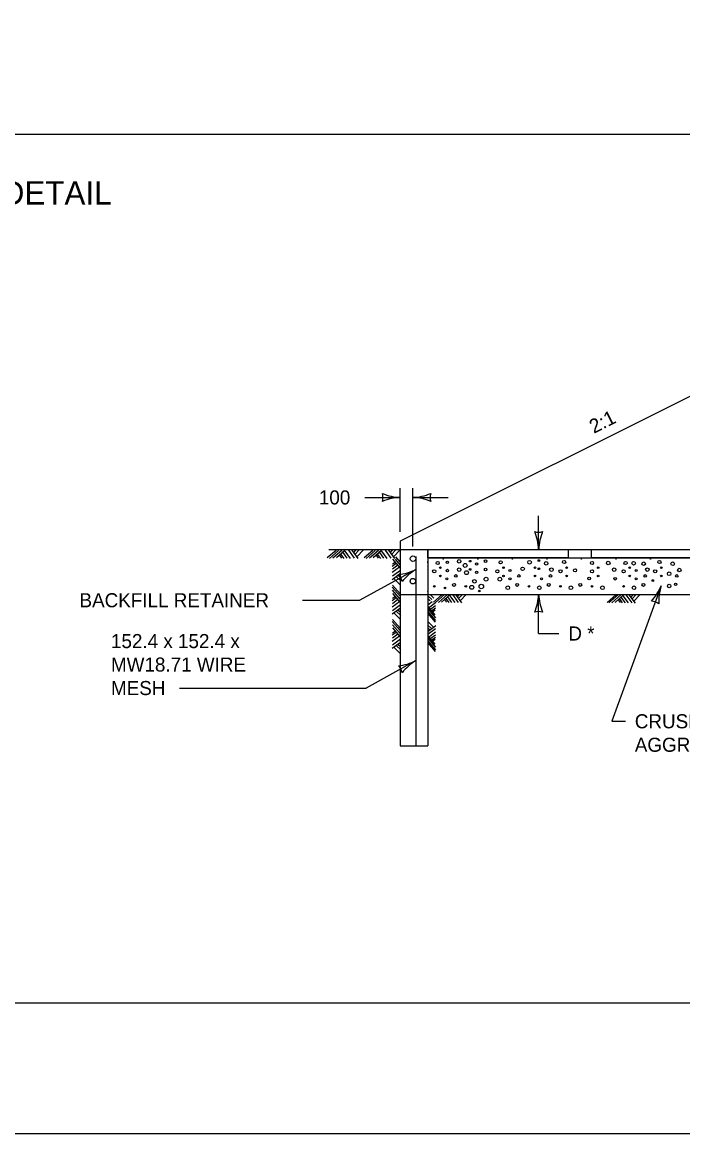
# Model space of a CAD drawing. Extents: x 49991.4 to 50021, y 49987.6 to 50011.4.
# Drawn here: x 50006.879 to 50009.692, y 49987.799 to 49992.532 of the extents above; entities that cross this region are included whole.
import ezdxf

# ---------------------------------------------------------------- set-up
doc = ezdxf.new("R2010")
doc.units = 0
for name, color, linetype in [('Level 1', 7, 'Continuous'), ('Level 2', 7, 'Continuous'), ('Level 3', 7, 'Continuous')]:
    doc.layers.add(name, color=color, linetype=linetype)

msp = doc.modelspace()

# ---------------------------------------------------------------- linework, layer by layer
at = {"layer": 'Level 1'}
for p, q in [((50010.2683, 49991.2116), (50008.4885, 49990.3217)), ((50008.2151, 49990.2827), (50008.1781, 49990.2505)), ((50008.1844, 49990.287), (50008.6055, 49990.287)), ((50008.226, 49990.2827), (50008.1871, 49990.2488)), ((50008.2398, 49990.2829), (50008.2018, 49990.2498)), ((50008.253, 49990.2831), (50008.2167, 49990.2515)), ((50008.2678, 49990.2835), (50008.2923, 49990.2498)), ((50008.2821, 49990.2837), (50008.3081, 49990.248)), ((50008.2891, 49990.2722), (50008.2999, 49990.2837)), ((50008.2956, 49990.2654), (50008.3139, 49990.2847)), ((50008.3051, 49990.2563), (50008.3305, 49990.2833)), ((50008.3715, 49990.2827), (50008.3344, 49990.2505)), ((50008.3824, 49990.2827), (50008.3435, 49990.2488)), ((50008.3962, 49990.2829), (50008.3581, 49990.2498)), ((50008.4094, 49990.2831), (50008.3729, 49990.2515)), ((50008.424, 49990.2835), (50008.4486, 49990.2498)), ((50008.4383, 49990.2837), (50008.4645, 49990.248)), ((50008.4454, 49990.2722), (50008.4562, 49990.2837)), ((50008.4519, 49990.2654), (50008.4701, 49990.2847)), ((50008.4615, 49990.2563), (50008.4869, 49990.2833)), ((50008.4885, 49990.3217), (50008.4885, 49989.4513)), ((50008.4885, 49990.2827), (50008.4885, 49990.2827)), ((50008.6055, 49990.287), (50008.6055, 49989.4513)), ((50008.6055, 49990.287), (50010.568, 49990.287)), ((50008.6055, 49990.287), (50009.2036, 49990.287)), ((50008.6055, 49990.2515), (50008.6055, 49990.287)), ((50009.2036, 49990.287), (50009.2036, 49990.2515)), ((50009.303, 49990.2515), (50009.303, 49990.287)), ((50009.303, 49990.287), (50010.568, 49990.287)), ((50008.2295, 49990.2621), (50008.238, 49990.2504)), ((50008.2357, 49990.266), (50008.2482, 49990.2488)), ((50008.2435, 49990.2732), (50008.2608, 49990.2494)), ((50008.2531, 49990.2797), (50008.2757, 49990.2488)), ((50008.3859, 49990.2621), (50008.3944, 49990.2504)), ((50008.3921, 49990.266), (50008.4046, 49990.2488)), ((50008.3998, 49990.2732), (50008.4172, 49990.2494)), ((50008.4094, 49990.2797), (50008.4319, 49990.2488)), ((50008.4889, 49990.2092), (50008.4573, 49990.2456)), ((50008.4887, 49990.2216), (50008.4682, 49990.2451)), ((50008.4885, 49990.2344), (50008.4703, 49990.2553)), ((50008.5553, 49990.257), (50008.5553, 49989.4513)), ((50008.6055, 49990.2515), (50010.568, 49990.2515)), ((50009.2036, 49990.2515), (50008.6055, 49990.2515)), ((50008.6055, 49990.2472), (50008.6055, 49990.2472)), ((50010.568, 49990.2515), (50009.303, 49990.2515)), ((50008.4717, 49990.227), (50008.4546, 49990.2144)), ((50008.4855, 49990.211), (50008.4546, 49990.1885)), ((50008.4789, 49990.2198), (50008.4551, 49990.2025)), ((50008.4892, 49990.1973), (50008.4556, 49990.1727)), ((50008.4678, 49990.2326), (50008.4562, 49990.2241)), ((50008.4895, 49990.1839), (50008.4538, 49990.1579)), ((50008.4621, 49990.1623), (50008.4889, 49990.1369)), ((50008.4712, 49990.1711), (50008.4905, 49990.1527)), ((50008.478, 49990.1768), (50008.4894, 49990.166)), ((50008.4885, 49990.0879), (50008.4546, 49990.1268)), ((50008.4887, 49990.0749), (50008.4556, 49990.113)), ((50008.4885, 49990.0982), (50008.4562, 49990.1352)), ((50008.4889, 49990.0627), (50008.4573, 49990.0991)), ((50008.4885, 49990.0955), (50010.568, 49990.0955)), ((50008.6319, 49990.0801), (50008.6156, 49990.0955)), ((50008.6675, 49990.0944), (50008.6305, 49990.0621)), ((50008.6773, 49990.0944), (50008.6384, 49990.0604)), ((50008.6896, 49990.0945), (50008.6515, 49990.0614)), ((50008.7012, 49990.0948), (50008.6648, 49990.063)), ((50008.711, 49990.0951), (50008.7355, 49990.0615)), ((50008.7236, 49990.0953), (50008.7497, 49990.0597)), ((50008.7307, 49990.0839), (50008.7415, 49990.0953)), ((50008.7361, 49990.077), (50008.7536, 49990.0955)), ((50008.7442, 49990.0678), (50008.7697, 49990.0948)), ((50009.4285, 49990.0931), (50009.3904, 49990.06)), ((50009.4401, 49990.0934), (50009.4037, 49990.0616)), ((50009.4499, 49990.0937), (50009.4745, 49990.0601)), ((50009.4627, 49990.0939), (50009.4887, 49990.0583)), ((50009.4697, 49990.0825), (50009.4805, 49990.0939)), ((50009.475, 49990.0756), (50009.4934, 49990.095)), ((50009.4832, 49990.0664), (50009.5086, 49990.0934)), ((50008.4717, 49990.0805), (50008.4546, 49990.0679)), ((50008.4855, 49990.0644), (50008.4546, 49990.0418)), ((50008.4789, 49990.0733), (50008.4551, 49990.056)), ((50008.4892, 49990.0507), (50008.4556, 49990.0262)), ((50008.4678, 49990.0861), (50008.4562, 49990.0776)), ((50008.6227, 49990.0731), (50008.6055, 49990.0894)), ((50008.6159, 49990.0687), (50008.6055, 49990.0786)), ((50008.6055, 49990.0508), (50008.6244, 49990.0646)), ((50008.6085, 49990.0388), (50008.6393, 49990.0613)), ((50008.6151, 49990.0316), (50008.6388, 49990.0489)), ((50008.6778, 49990.0737), (50008.6863, 49990.0621)), ((50008.6832, 49990.0776), (50008.6957, 49990.0604)), ((50008.6898, 49990.0848), (50008.7071, 49990.061)), ((50008.6981, 49990.0914), (50008.7206, 49990.0605)), ((50009.4064, 49990.093), (50009.3694, 49990.0607)), ((50009.4162, 49990.093), (50009.3773, 49990.059)), ((50009.4168, 49990.0723), (50009.4252, 49990.0607)), ((50009.4221, 49990.0762), (50009.4346, 49990.059)), ((50009.4287, 49990.0834), (50009.4461, 49990.0596)), ((50009.437, 49990.09), (50009.4595, 49990.0591)), ((50008.4895, 49990.0374), (50008.4538, 49990.0113)), ((50008.4621, 49990.0158), (50008.4889, 49989.9903)), ((50008.4712, 49990.0244), (50008.4905, 49990.0062)), ((50008.478, 49990.0303), (50008.4894, 49990.0195)), ((50008.6055, 49990.044), (50008.6367, 49990.0082)), ((50008.6055, 49990.034), (50008.6383, 49989.9962)), ((50008.6055, 49990.0232), (50008.6393, 49989.9845)), ((50008.6055, 49990.0143), (50008.6377, 49989.9774)), ((50008.6223, 49990.0259), (50008.6393, 49990.0383)), ((50008.6261, 49990.0213), (50008.6377, 49990.0298)), ((50008.4885, 49989.9414), (50008.4546, 49989.9803)), ((50008.4887, 49989.9284), (50008.4556, 49989.9665)), ((50008.4885, 49989.9517), (50008.4562, 49989.9887)), ((50008.4889, 49989.9162), (50008.4573, 49989.9525)), ((50008.6319, 49989.9551), (50008.6055, 49989.98)), ((50008.6227, 49989.9482), (50008.6055, 49989.9645)), ((50008.6055, 49989.9374), (50008.6401, 49989.9626)), ((50008.6159, 49989.9438), (50008.6055, 49989.9537)), ((50008.4717, 49989.9338), (50008.4546, 49989.9213)), ((50008.4855, 49989.9179), (50008.4546, 49989.8953)), ((50008.4789, 49989.9267), (50008.4551, 49989.9093)), ((50008.4892, 49989.9042), (50008.4556, 49989.8797)), ((50008.4678, 49989.9396), (50008.4562, 49989.9311)), ((50008.6055, 49989.9259), (50008.6383, 49989.9499)), ((50008.6055, 49989.9191), (50008.6367, 49989.8832)), ((50008.6055, 49989.9089), (50008.6383, 49989.8712)), ((50008.6085, 49989.9138), (50008.6393, 49989.9363)), ((50008.6151, 49989.9066), (50008.6388, 49989.924)), ((50008.6223, 49989.9009), (50008.6393, 49989.9134)), ((50008.6261, 49989.8964), (50008.6377, 49989.9049)), ((50008.4895, 49989.8909), (50008.4538, 49989.8648)), ((50008.4621, 49989.8693), (50008.4889, 49989.8437)), ((50008.4712, 49989.8779), (50008.4905, 49989.8597)), ((50008.478, 49989.8838), (50008.4894, 49989.873)), ((50008.6055, 49989.8983), (50008.6393, 49989.8594)), ((50008.6055, 49989.8894), (50008.6377, 49989.8523)), ((50008.4885, 49989.6899), (50008.4885, 49989.6899)), ((50008.4885, 49989.4513), (50008.6055, 49989.4513))]:
    msp.add_line(p, q, dxfattribs=at)
for points in [[(49999.3835, 49998.9992), (50016.7501, 49998.9992), (50016.7501, 49987.7988), (49999.3835, 49987.7988)], [(49999.5613, 49992.0549), (50014.5211, 49992.0549), (50014.5211, 49988.3552), (49999.5613, 49988.3552)]]:
    msp.add_lwpolyline(points, close=True, dxfattribs=at)
for centre, radius in [((50008.5429, 49990.2475), 0.0116), ((50008.6482, 49990.229), 0.00684), ((50008.6893, 49990.232), 0.00552), ((50008.7395, 49990.2361), 0.00765), ((50008.7863, 49990.2369), 0.00341), ((50008.8522, 49990.2369), 0.00552), ((50008.9164, 49990.2319), 0.00684), ((50009.0396, 49990.2323), 0.00765), ((50009.0793, 49990.2397), 0.00346), ((50009.1102, 49990.2276), 0.00765), ((50009.1867, 49990.2333), 0.00684), ((50009.3056, 49990.229), 0.00684), ((50009.3746, 49990.229), 0.00765), ((50009.4485, 49990.229), 0.00684), ((50009.4829, 49990.2282), 0.00766), ((50009.5928, 49990.2333), 0.00684), ((50008.6335, 49990.1939), 0.00684), ((50008.6595, 49990.2092), 0.00341), ((50008.6893, 49990.1968), 0.00552), ((50008.7395, 49990.2009), 0.00765), ((50008.7654, 49990.2189), 0.00824), ((50008.771, 49990.1879), 0.00824), ((50008.7863, 49990.2017), 0.00341), ((50008.8139, 49990.2246), 0.0046), ((50008.8139, 49990.1895), 0.0046), ((50008.8522, 49990.2017), 0.00552), ((50008.9023, 49990.1939), 0.00684), ((50008.9284, 49990.2092), 0.00341), ((50008.9559, 49990.197), 0.0046), ((50009.0101, 49990.2042), 0.00765), ((50009.0628, 49990.2092), 0.00341), ((50009.0793, 49990.2045), 0.00346), ((50009.1327, 49990.2009), 0.00765), ((50009.1712, 49990.1939), 0.00684), ((50009.1972, 49990.2092), 0.00341), ((50009.2331, 49990.1981), 0.00684), ((50009.3056, 49990.1939), 0.00684), ((50009.3317, 49990.2092), 0.00341), ((50009.3999, 49990.2009), 0.00765), ((50009.4401, 49990.1939), 0.00684), ((50009.4661, 49990.2092), 0.00341), ((50009.4937, 49990.197), 0.0046), ((50009.5257, 49990.2261), 0.00765), ((50009.5411, 49990.2008), 0.00765), ((50009.5745, 49990.1939), 0.00684), ((50009.6005, 49990.2092), 0.00341), ((50009.6342, 49990.1832), 0.00766), ((50009.6491, 49990.2259), 0.00765), ((50009.6773, 49990.1992), 0.00765), ((50008.5424, 49990.1518), 0.0116), ((50008.6595, 49990.174), 0.00341), ((50008.6871, 49990.1618), 0.0046), ((50008.7177, 49990.1359), 0.00613), ((50008.7253, 49990.174), 0.00552), ((50008.8047, 49990.1513), 0.00766), ((50008.8543, 49990.1603), 0.00824), ((50008.913, 49990.1603), 0.00824), ((50008.9284, 49990.174), 0.00341), ((50008.9559, 49990.1618), 0.0046), ((50008.9866, 49990.1359), 0.00613), ((50008.9942, 49990.174), 0.00552), ((50009.0628, 49990.174), 0.00341), ((50009.0904, 49990.1618), 0.0046), ((50009.121, 49990.1359), 0.00613), ((50009.1286, 49990.174), 0.00552), ((50009.1972, 49990.174), 0.00341), ((50009.2554, 49990.1359), 0.00613), ((50009.2932, 49990.1634), 0.00552), ((50009.3317, 49990.174), 0.00341), ((50009.4043, 49990.1622), 0.00552), ((50009.4661, 49990.174), 0.00341), ((50009.4937, 49990.1618), 0.0046), ((50009.5243, 49990.1359), 0.00613), ((50009.532, 49990.174), 0.00552), ((50009.5646, 49990.1544), 0.00341), ((50009.6005, 49990.174), 0.00341), ((50009.6618, 49990.1382), 0.00552), ((50009.6664, 49990.174), 0.00552), ((50008.6335, 49990.1298), 0.00341), ((50008.6794, 49990.123), 0.00341), ((50008.7679, 49990.1298), 0.00341), ((50008.7932, 49990.1256), 0.00824), ((50008.8254, 49990.1096), 0.00341), ((50008.834, 49990.1288), 0.00968), ((50008.9467, 49990.1237), 0.00766), ((50009.0368, 49990.1298), 0.00341), ((50009.0812, 49990.1237), 0.00766), ((50009.1712, 49990.1298), 0.00341), ((50009.2156, 49990.1237), 0.00766), ((50009.3056, 49990.1298), 0.00341), ((50009.35, 49990.1237), 0.00766), ((50009.4401, 49990.1298), 0.00341), ((50009.4845, 49990.1237), 0.00766), ((50009.6342, 49990.1312), 0.00766)]:
    msp.add_circle(centre, radius, dxfattribs=at)
for centre, radius, start, end in [((50008.6037, 49990.233), 0.0031, 305.1264, 54.8736), ((50008.6721, 49990.2487), 0.00283, 211.7965, 328.2035), ((50008.8192, 49990.2487), 0.00283, 211.7965, 328.2035), ((50008.9663, 49990.2487), 0.00283, 211.7965, 328.2035), ((50009.1134, 49990.2487), 0.00283, 211.7965, 328.2035), ((50009.2604, 49990.2487), 0.00283, 211.7965, 328.2035), ((50009.4075, 49990.2487), 0.00283, 211.7965, 328.2035), ((50009.5546, 49990.2487), 0.00283, 211.7965, 328.2035), ((50008.6001, 49990.2076), 0.00765, 314.8637, 45.1363), ((50008.6001, 49990.1023), 0.00765, 14.7763, 45.1363)]:
    msp.add_arc(centre, radius, start, end, dxfattribs=at)
at = {"layer": 'Level 3'}
for p, q in [((50008.4885, 49990.3617), (50008.4885, 49990.5483)), ((50008.5426, 49990.2991), (50008.5426, 49990.5483)), ((50008.3385, 49990.5083), (50008.4885, 49990.5083)), ((50008.5426, 49990.5083), (50008.6926, 49990.5083)), ((50009.0782, 49990.287), (50009.0782, 49990.4299)), ((50008.5553, 49990.2018), (50008.3171, 49990.0706)), ((50009.0782, 49989.929), (50009.0782, 49990.0955)), ((50009.6001, 49990.1322), (50009.3904, 49989.5552)), ((50008.0723, 49990.0706), (50008.3171, 49990.0706)), ((50009.0782, 49989.929), (50009.1647, 49989.929)), ((50008.5553, 49989.8133), (50008.3439, 49989.6968)), ((50007.5487, 49989.6967), (50008.3438, 49989.6967)), ((50009.3904, 49989.5552), (50009.4478, 49989.5552))]:
    msp.add_line(p, q, dxfattribs=at)
for centre, radius, start, end in [((50008.4977, 49990.7305), 0.2223, 247.456, 267.6395), ((50008.3603, 49990.5083), 0.0548, 342.1388, 17.8612), ((50008.5311, 49990.741), 0.233, 272.8273, 292.0772), ((50008.6708, 49990.5083), 0.0548, 162.1388, 197.8612), ((50008.5, 49990.2756), 0.233, 92.8273, 112.0772), ((50008.5335, 49990.2862), 0.2223, 67.456, 87.6395), ((50009.0782, 49990.4152), 0.0548, 252.1388, 287.8612), ((50008.8455, 49990.2755), 0.233, 2.8273, 22.0772), ((50009.3004, 49990.2779), 0.2223, 157.456, 177.6395), ((50008.4562, 49990.4008), 0.2223, 276.3053, 296.4888), ((50008.6777, 49990.0035), 0.233, 121.6766, 140.9265), ((50008.443, 49990.14), 0.0548, 10.9881, 46.7105), ((50008.8561, 49990.1047), 0.2223, 337.456, 357.6395), ((50009.3109, 49990.107), 0.233, 182.8273, 202.0772), ((50009.3945, 49990.2167), 0.2223, 317.4833, 337.6668), ((50009.8228, 49990.0635), 0.233, 162.8546, 182.1044), ((50009.5563, 49990.0117), 0.0548, 52.1661, 87.8884), ((50009.0782, 49989.9673), 0.0548, 72.1388, 107.8612), ((50008.4562, 49990.0123), 0.2223, 276.3053, 296.4888), ((50008.6777, 49989.615), 0.233, 121.6766, 140.9265), ((50008.443, 49989.7514), 0.0548, 10.9881, 46.7105)]:
    msp.add_arc(centre, radius, start, end, dxfattribs=at)

# ---------------------------------------------------------------- texts
at = {"layer": 'Level 2'}
for s, height, p in [('BACKFILL RETAINER & CUTOFF WALL DETAIL', 0.1, (50004.3019, 49991.755)), ('100', 0.06, (50008.142, 49990.4783)), ('BACKFILL RETAINER', 0.06, (50007.1226, 49990.0406)), ('D *', 0.06, (50009.2047, 49989.899)), ('152.4 x 152.4 x ', 0.06, (50007.2566, 49989.8667)), ('MW18.71 WIRE', 0.06, (50007.2566, 49989.7667)), ('MESH', 0.06, (50007.2566, 49989.6667)), ('CRUSHED', 0.06, (50009.4878, 49989.5252)), ('AGGREGATE COURSE', 0.06, (50009.4878, 49989.4252))]:
    msp.add_text(s, height=height, dxfattribs=at).set_placement(p)
msp.add_text('2:1', height=0.06, rotation=26.5651, dxfattribs=at).set_placement((50009.3132, 49990.7788))

doc.saveas('drawing.dxf')
